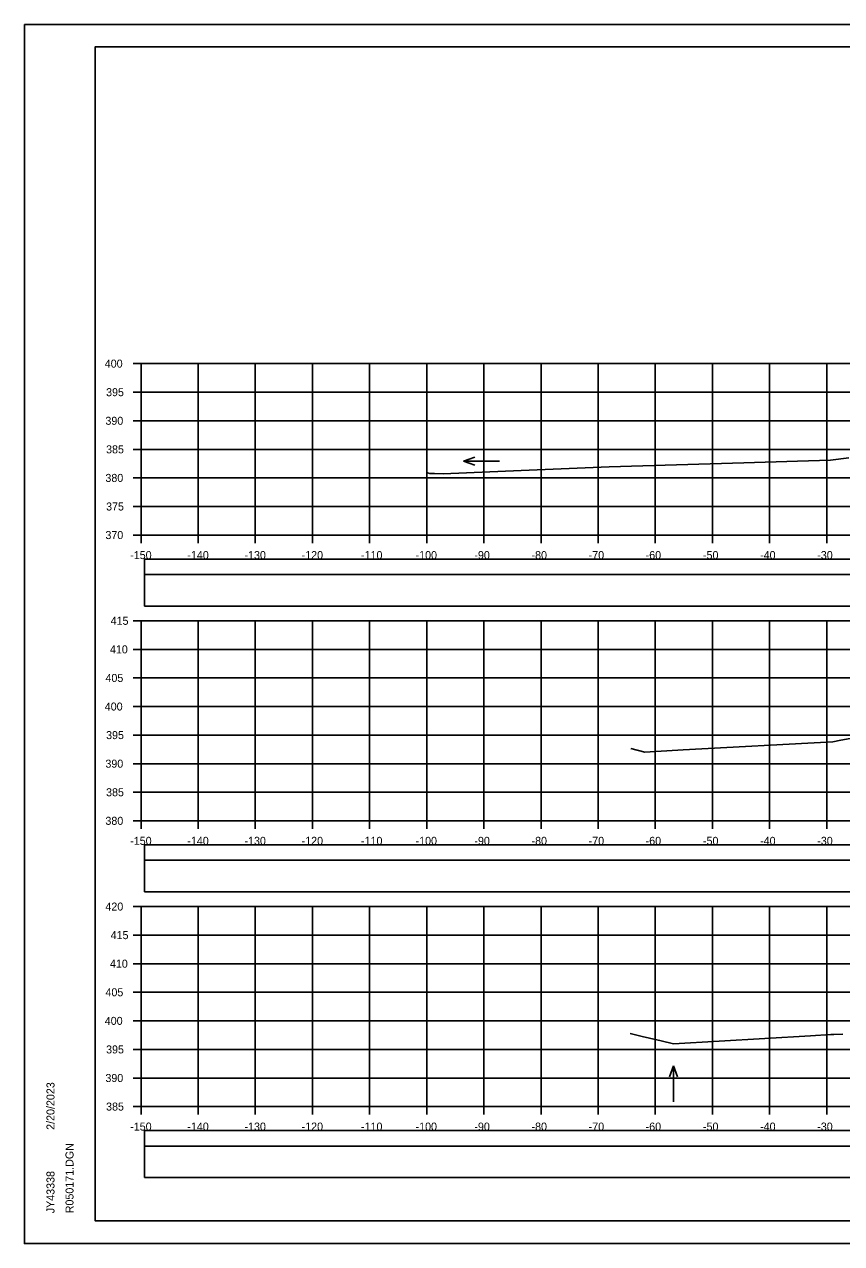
# Model space of a CAD drawing. Extents: x -37291014 to -37290680, y -936053 to -933067.
# Drawn here: x -37291013.5 to -37290870.5, y -935840 to -935626.6 of the extents above; entities that cross this region are included whole.
import ezdxf

# ---------------------------------------------------------------- set-up
doc = ezdxf.new("R2010")
doc.units = 0
for name, color, linetype in [('Default', 7, 'Continuous'), ('R_Axis', 7, 'Continuous'), ('R_Axis Annot', 7, 'Continuous'), ('R_Border', 7, 'Continuous'), ('R_Exist Surface', 7, 'Continuous'), ('R_Grid', 7, 'Continuous'), ('R_No Plot', 7, 'Continuous'), ('R_Water Annot', 7, 'Continuous')]:
    doc.layers.add(name, color=color, linetype=linetype)

msp = doc.modelspace()

# ---------------------------------------------------------------- linework, layer by layer
at = {"layer": 'Default'}
for points in [[(-37290992.48, -935722.89), (-37290693.72, -935722.89), (-37290693.72, -935720.19), (-37290992.48, -935720.19)], [(-37290992.48, -935728.41), (-37290693.72, -935728.41), (-37290693.72, -935722.89), (-37290992.48, -935722.89)], [(-37290992.48, -935772.89), (-37290693.72, -935772.89), (-37290693.72, -935770.19), (-37290992.48, -935770.19)], [(-37290992.48, -935778.41), (-37290693.72, -935778.41), (-37290693.72, -935772.89), (-37290992.48, -935772.89)], [(-37290992.48, -935822.89), (-37290693.72, -935822.89), (-37290693.72, -935820.19), (-37290992.48, -935820.19)], [(-37290992.48, -935828.41), (-37290693.72, -935828.41), (-37290693.72, -935822.89), (-37290992.48, -935822.89)]]:
    msp.add_lwpolyline(points, close=True, dxfattribs=at)
at = {"layer": 'R_Axis'}
for p, q in [((-37290994.5, -935685.99), (-37290993.1, -935685.99)), ((-37290993.1, -935715.99), (-37290993.1, -935685.99)), ((-37290994.5, -935690.99), (-37290993.1, -935690.99)), ((-37290994.5, -935695.99), (-37290993.1, -935695.99)), ((-37290994.5, -935700.99), (-37290993.1, -935700.99)), ((-37290994.5, -935705.99), (-37290993.1, -935705.99)), ((-37290994.5, -935710.99), (-37290993.1, -935710.99)), ((-37290994.5, -935715.99), (-37290993.1, -935715.99)), ((-37290993.1, -935715.99), (-37290693.1, -935715.99)), ((-37290993.1, -935717.39), (-37290993.1, -935715.99)), ((-37290983.1, -935717.39), (-37290983.1, -935715.99)), ((-37290973.1, -935717.39), (-37290973.1, -935715.99)), ((-37290963.1, -935717.39), (-37290963.1, -935715.99)), ((-37290953.1, -935717.39), (-37290953.1, -935715.99)), ((-37290943.1, -935717.39), (-37290943.1, -935715.99)), ((-37290933.1, -935717.39), (-37290933.1, -935715.99)), ((-37290923.1, -935717.39), (-37290923.1, -935715.99)), ((-37290913.1, -935717.39), (-37290913.1, -935715.99)), ((-37290903.1, -935717.39), (-37290903.1, -935715.99)), ((-37290893.1, -935717.39), (-37290893.1, -935715.99)), ((-37290883.1, -935717.39), (-37290883.1, -935715.99)), ((-37290873.1, -935717.39), (-37290873.1, -935715.99)), ((-37290994.5, -935730.99), (-37290993.1, -935730.99)), ((-37290993.1, -935765.99), (-37290993.1, -935730.99)), ((-37290994.5, -935735.99), (-37290993.1, -935735.99)), ((-37290994.5, -935740.99), (-37290993.1, -935740.99)), ((-37290994.5, -935745.99), (-37290993.1, -935745.99)), ((-37290994.5, -935750.99), (-37290993.1, -935750.99)), ((-37290994.5, -935755.99), (-37290993.1, -935755.99)), ((-37290994.5, -935760.99), (-37290993.1, -935760.99)), ((-37290994.5, -935765.99), (-37290993.1, -935765.99)), ((-37290993.1, -935765.99), (-37290693.1, -935765.99)), ((-37290993.1, -935767.39), (-37290993.1, -935765.99)), ((-37290983.1, -935767.39), (-37290983.1, -935765.99)), ((-37290973.1, -935767.39), (-37290973.1, -935765.99)), ((-37290963.1, -935767.39), (-37290963.1, -935765.99)), ((-37290953.1, -935767.39), (-37290953.1, -935765.99)), ((-37290943.1, -935767.39), (-37290943.1, -935765.99)), ((-37290933.1, -935767.39), (-37290933.1, -935765.99)), ((-37290923.1, -935767.39), (-37290923.1, -935765.99)), ((-37290913.1, -935767.39), (-37290913.1, -935765.99)), ((-37290903.1, -935767.39), (-37290903.1, -935765.99)), ((-37290893.1, -935767.39), (-37290893.1, -935765.99)), ((-37290883.1, -935767.39), (-37290883.1, -935765.99)), ((-37290873.1, -935767.39), (-37290873.1, -935765.99)), ((-37290994.5, -935780.99), (-37290993.1, -935780.99)), ((-37290993.1, -935815.99), (-37290993.1, -935780.99)), ((-37290994.5, -935785.99), (-37290993.1, -935785.99)), ((-37290994.5, -935790.99), (-37290993.1, -935790.99)), ((-37290994.5, -935795.99), (-37290993.1, -935795.99)), ((-37290994.5, -935800.99), (-37290993.1, -935800.99)), ((-37290994.5, -935805.99), (-37290993.1, -935805.99)), ((-37290994.5, -935810.99), (-37290993.1, -935810.99)), ((-37290994.5, -935815.99), (-37290993.1, -935815.99)), ((-37290993.1, -935815.99), (-37290693.1, -935815.99)), ((-37290993.1, -935817.39), (-37290993.1, -935815.99)), ((-37290983.1, -935817.39), (-37290983.1, -935815.99)), ((-37290973.1, -935817.39), (-37290973.1, -935815.99)), ((-37290963.1, -935817.39), (-37290963.1, -935815.99)), ((-37290953.1, -935817.39), (-37290953.1, -935815.99)), ((-37290943.1, -935817.39), (-37290943.1, -935815.99)), ((-37290933.1, -935817.39), (-37290933.1, -935815.99)), ((-37290923.1, -935817.39), (-37290923.1, -935815.99)), ((-37290913.1, -935817.39), (-37290913.1, -935815.99)), ((-37290903.1, -935817.39), (-37290903.1, -935815.99)), ((-37290893.1, -935817.39), (-37290893.1, -935815.99)), ((-37290883.1, -935817.39), (-37290883.1, -935815.99)), ((-37290873.1, -935817.39), (-37290873.1, -935815.99))]:
    msp.add_line(p, q, dxfattribs=at)
at = {"layer": 'R_Border'}
for p, q in [((-37291001.1, -935630.53), (-37290684.92, -935630.53)), ((-37291001.1, -935835.99), (-37291001.1, -935630.53)), ((-37291001.1, -935835.99), (-37291001.1, -935835.99)), ((-37290684.92, -935835.99), (-37291001.1, -935835.99))]:
    msp.add_line(p, q, dxfattribs=at)
at = {"layer": 'R_Exist Surface'}
for points in [[(-37290942.95, -935705.11), (-37290942.54, -935705.21), (-37290941.76, -935705.23), (-37290940.23, -935705.27), (-37290936.12, -935705.09), (-37290926.56, -935704.69), (-37290911.15, -935704.03), (-37290887.6, -935703.33), (-37290878.23, -935703.05), (-37290872.44, -935702.89), (-37290869.26, -935702.47)], [(-37290907.38, -935753.35), (-37290904.93, -935753.95), (-37290898.21, -935753.59), (-37290872.06, -935752.16), (-37290870.65, -935751.9), (-37290860.31, -935750)], [(-37290907.5, -935803.18), (-37290905.37, -935803.7), (-37290902.05, -935804.5), (-37290899.93, -935805.01), (-37290875.93, -935803.63), (-37290872.41, -935803.39), (-37290871.85, -935803.39), (-37290870.31, -935803.32)]]:
    msp.add_lwpolyline(points, dxfattribs=at)
at = {"layer": 'R_Grid'}
for p, q in [((-37290993.1, -935685.99), (-37290693.1, -935685.99)), ((-37290993.1, -935715.99), (-37290993.1, -935685.99)), ((-37290983.1, -935715.99), (-37290983.1, -935685.99)), ((-37290973.1, -935715.99), (-37290973.1, -935685.99)), ((-37290963.1, -935715.99), (-37290963.1, -935685.99)), ((-37290953.1, -935715.99), (-37290953.1, -935685.99)), ((-37290943.1, -935715.99), (-37290943.1, -935685.99)), ((-37290933.1, -935715.99), (-37290933.1, -935685.99)), ((-37290923.1, -935715.99), (-37290923.1, -935685.99)), ((-37290913.1, -935715.99), (-37290913.1, -935685.99)), ((-37290903.1, -935715.99), (-37290903.1, -935685.99)), ((-37290893.1, -935715.99), (-37290893.1, -935685.99)), ((-37290883.1, -935715.99), (-37290883.1, -935685.99)), ((-37290873.1, -935715.99), (-37290873.1, -935685.99)), ((-37290993.1, -935690.99), (-37290693.1, -935690.99)), ((-37290993.1, -935695.99), (-37290693.1, -935695.99)), ((-37290993.1, -935700.99), (-37290693.1, -935700.99)), ((-37290993.1, -935705.99), (-37290693.1, -935705.99)), ((-37290993.1, -935710.99), (-37290693.1, -935710.99)), ((-37290993.1, -935715.99), (-37290693.1, -935715.99)), ((-37290993.1, -935730.99), (-37290693.1, -935730.99)), ((-37290993.1, -935765.99), (-37290993.1, -935730.99)), ((-37290983.1, -935765.99), (-37290983.1, -935730.99)), ((-37290973.1, -935765.99), (-37290973.1, -935730.99)), ((-37290963.1, -935765.99), (-37290963.1, -935730.99)), ((-37290953.1, -935765.99), (-37290953.1, -935730.99)), ((-37290943.1, -935765.99), (-37290943.1, -935730.99)), ((-37290933.1, -935765.99), (-37290933.1, -935730.99)), ((-37290923.1, -935765.99), (-37290923.1, -935730.99)), ((-37290913.1, -935765.99), (-37290913.1, -935730.99)), ((-37290903.1, -935765.99), (-37290903.1, -935730.99)), ((-37290893.1, -935765.99), (-37290893.1, -935730.99)), ((-37290883.1, -935765.99), (-37290883.1, -935730.99)), ((-37290873.1, -935765.99), (-37290873.1, -935730.99)), ((-37290993.1, -935735.99), (-37290693.1, -935735.99)), ((-37290993.1, -935740.99), (-37290693.1, -935740.99)), ((-37290993.1, -935745.99), (-37290693.1, -935745.99)), ((-37290993.1, -935750.99), (-37290693.1, -935750.99)), ((-37290993.1, -935755.99), (-37290693.1, -935755.99)), ((-37290993.1, -935760.99), (-37290693.1, -935760.99)), ((-37290993.1, -935765.99), (-37290693.1, -935765.99)), ((-37290993.1, -935780.99), (-37290693.1, -935780.99)), ((-37290993.1, -935815.99), (-37290993.1, -935780.99)), ((-37290983.1, -935815.99), (-37290983.1, -935780.99)), ((-37290973.1, -935815.99), (-37290973.1, -935780.99)), ((-37290963.1, -935815.99), (-37290963.1, -935780.99)), ((-37290953.1, -935815.99), (-37290953.1, -935780.99)), ((-37290943.1, -935815.99), (-37290943.1, -935780.99)), ((-37290933.1, -935815.99), (-37290933.1, -935780.99)), ((-37290923.1, -935815.99), (-37290923.1, -935780.99)), ((-37290913.1, -935815.99), (-37290913.1, -935780.99)), ((-37290903.1, -935815.99), (-37290903.1, -935780.99)), ((-37290893.1, -935815.99), (-37290893.1, -935780.99)), ((-37290883.1, -935815.99), (-37290883.1, -935780.99)), ((-37290873.1, -935815.99), (-37290873.1, -935780.99)), ((-37290993.1, -935785.99), (-37290693.1, -935785.99)), ((-37290993.1, -935790.99), (-37290693.1, -935790.99)), ((-37290993.1, -935795.99), (-37290693.1, -935795.99)), ((-37290993.1, -935800.99), (-37290693.1, -935800.99)), ((-37290993.1, -935805.99), (-37290693.1, -935805.99)), ((-37290993.1, -935810.99), (-37290693.1, -935810.99)), ((-37290993.1, -935815.99), (-37290693.1, -935815.99))]:
    msp.add_line(p, q, dxfattribs=at)
at = {"layer": 'R_No Plot'}
for p, q in [((-37291013.5, -935626.63), (-37290680.17, -935626.63)), ((-37291013.5, -935839.96), (-37290680.17, -935839.96))]:
    msp.add_line(p, q, dxfattribs=at)
for points in [[(-37291013.51, -935626.63), (-37290680.17, -935626.63), (-37290680.17, -935839.97), (-37291013.51, -935839.97)], [(-37290767.18, -935630.53), (-37290747.56, -935630.53), (-37290747.56, -935640.41), (-37290731.45, -935640.41), (-37290708.25, -935640.41), (-37290708.25, -935664.74), (-37290684.92, -935664.74), (-37290684.92, -935835.99), (-37291001.1, -935835.99), (-37291001.1, -935630.53)]]:
    msp.add_lwpolyline(points, close=True, dxfattribs=at)
at = {"layer": 'R_Water Annot'}
for p, q in [((-37290936.64, -935703.03), (-37290934.71, -935702.33)), ((-37290930.35, -935703.03), (-37290936.64, -935703.03)), ((-37290936.64, -935703.03), (-37290934.71, -935703.73)), ((-37290899.93, -935808.87), (-37290900.63, -935810.79)), ((-37290899.93, -935815.15), (-37290899.93, -935808.87)), ((-37290899.93, -935808.87), (-37290899.23, -935810.79))]:
    msp.add_line(p, q, dxfattribs=at)

# ---------------------------------------------------------------- texts
at = {"layer": 'R_Axis Annot'}
for s, p in [('400', (-37290999.44, -935686.69)), ('395', (-37290999.21, -935691.69)), ('390', (-37290999.33, -935696.69)), ('385', (-37290999.21, -935701.69)), ('380', (-37290999.33, -935706.69)), ('375', (-37290999.21, -935711.69)), ('370', (-37290999.33, -935716.69)), ('-150', (-37290994.99, -935720.19)), ('-140', (-37290984.99, -935720.19)), ('-130', (-37290974.99, -935720.19)), ('-120', (-37290964.99, -935720.19)), ('-110', (-37290954.6, -935720.19)), ('-100', (-37290945.05, -935720.19)), ('-90', (-37290934.76, -935720.19)), ('-80', (-37290924.76, -935720.19)), ('-70', (-37290914.76, -935720.19)), ('-60', (-37290904.79, -935720.19)), ('-50', (-37290894.76, -935720.19)), ('-40', (-37290884.76, -935720.19)), ('-30', (-37290874.76, -935720.19)), ('415', (-37290998.42, -935731.69)), ('410', (-37290998.54, -935736.69)), ('405', (-37290999.32, -935741.69)), ('400', (-37290999.44, -935746.69)), ('395', (-37290999.21, -935751.69)), ('390', (-37290999.33, -935756.69)), ('385', (-37290999.21, -935761.69)), ('380', (-37290999.33, -935766.69)), ('-150', (-37290994.99, -935770.19)), ('-140', (-37290984.99, -935770.19)), ('-130', (-37290974.99, -935770.19)), ('-120', (-37290964.99, -935770.19)), ('-110', (-37290954.6, -935770.19)), ('-100', (-37290945.05, -935770.19)), ('-90', (-37290934.76, -935770.19)), ('-80', (-37290924.76, -935770.19)), ('-70', (-37290914.76, -935770.19)), ('-60', (-37290904.79, -935770.19)), ('-50', (-37290894.76, -935770.19)), ('-40', (-37290884.76, -935770.19)), ('-30', (-37290874.76, -935770.19)), ('420', (-37290999.33, -935781.69)), ('415', (-37290998.42, -935786.69)), ('410', (-37290998.54, -935791.69)), ('405', (-37290999.32, -935796.69)), ('400', (-37290999.44, -935801.69)), ('395', (-37290999.21, -935806.69)), ('390', (-37290999.33, -935811.69)), ('385', (-37290999.21, -935816.69)), ('-150', (-37290994.99, -935820.19)), ('-140', (-37290984.99, -935820.19)), ('-130', (-37290974.99, -935820.19)), ('-120', (-37290964.99, -935820.19)), ('-110', (-37290954.6, -935820.19)), ('-100', (-37290945.05, -935820.19)), ('-90', (-37290934.76, -935820.19)), ('-80', (-37290924.76, -935820.19)), ('-70', (-37290914.76, -935820.19)), ('-60', (-37290904.79, -935820.19)), ('-50', (-37290894.76, -935820.19)), ('-40', (-37290884.76, -935820.19)), ('-30', (-37290874.76, -935820.19))]:
    msp.add_text(s, height=1.4, dxfattribs=at).set_placement(p)
at = {"layer": 'R_Border'}
for s, p in [('2/20/2023', (-37291008.24, -935820.06)), ('R050171.DGN', (-37291004.91, -935834.66)), ('JY43338', (-37291008.24, -935834.66))]:
    msp.add_text(s, height=1.4, rotation=90, dxfattribs=at).set_placement(p)

doc.saveas('drawing.dxf')
